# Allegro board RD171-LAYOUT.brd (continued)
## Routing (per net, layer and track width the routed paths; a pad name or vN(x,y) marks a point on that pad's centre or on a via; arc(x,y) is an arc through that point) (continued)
CS: length 14.7
  CONDUCTIVE4 w0.6: v1(249.9,16.55) 249.45,16.55 249,17 249,24.8 v1(248.75,25.05)
  BOTTOM w0.4: v1(249.9,16.55) R67.2
  BOTTOM w0.6: v1(248.75,25.05) R185.2 248.75,27.6 248.05,28.3 D14.C
CSA: length 131.4
  TOP w0.3: 135.45,43.67 135.45,42.95 135,42.5 v1(129.4,42.5)
  TOP w0.4: v1(109.8,80.55) 109.8,79.3 109.2,78.7 TP2.1
  TOP w0.5: 136.7,43.9 D33.C 135.4,43.9
  TOP w0.8: D33.C 135.45,43.67
  CONDUCTIVE3 w0.3: v1(154.2,3.25) 150.45,3.25 150,3.7 150,34.95 144.5,40.45 131.45,40.45 v1(129.4,42.5) 129,42.1 118.68,42.1 108.45,52.33 108.45,79.2 v1(109.8,80.55)
  BOTTOM w0.3: 109.8,81.87 v1(109.8,80.55) ; v1(154.2,3.25) 154.2,1.95 153.95,1.7 153.34,1.7 ; 110.05,82.7 111.14,82.7
  BOTTOM w0.5: 111.14,82.7 111.3,82.7
  BOTTOM w0.58: 153.34,1.7 R170.1 153.14,1.7
  BOTTOM w1.1: 110.05,82.7 R7.2 109.8,81.87
CSB: length 103.6
  TOP w0.3: D31.C 150,39.35 150.35,39 v1(150.85,39)
  TOP w0.5: R83.1 D31.C
  TOP w0.6: v1(126.35,77.65) 124.7,77.65
  CONDUCTIVE3 w0.3: v1(153.3,4.2) 153.05,4.45 153.05,24.1 151.7,25.45 151.7,38.15 v1(150.85,39) 145,44.85 132.4,44.85 125.05,52.2 125.05,74.2 126.8,75.95 126.8,77.2 v1(126.35,77.65)
  BOTTOM w0.3: D12.C 128.45,81.05 127.6,80.2 ; v1(126.35,77.65) 126.35,78.05 127.55,79.25
  BOTTOM w0.4: 153.18,3.08 153.18,3.85 v1(153.3,4.2)
FG2: length 13.4
  TOP w2: C79.1 23.4,3.95 11.5,3.95
  vias: v2(8,4)
FG3: length 84.1
  TOP w1.45: 76.38,43.25 78.03,41.6 C64.1 ; 76.38,43.25 76.4,43.25 ; 76.38,43.25 C32.1 65.5,43.25 ; 61.25,48.5 C78.1
  CONDUCTIVE4 w1.45: C32.1 76.38,43.25 78.03,41.6 C64.1
  CONDUCTIVE5 w1.45: C64.1 78.03,41.6 76.38,43.25 C32.1
  BOTTOM w1.45: 65.5,43.25 C32.1 76.38,43.25 ; 76.4,43.25 78.05,41.6 C64.1 ; 61.25,48.5 C78.1
  vias: v2(63,45.5)
FG4: length 109.7
  TOP w2: v2(77.9,4) C31.1
  CONDUCTIVE4 w1.5: C63.1 111.1,1.25 80.1,1.25
  CONDUCTIVE5 w1.5: 80.1,1.25 111.1,1.25 C63.1
  BOTTOM w1.5: 80.1,1.25 111.1,1.25 C63.1
  BOTTOM w2: v2(77.9,4) C31.1
FG5: length 4.6
  BOTTOM w1.45: C101.2 178.25,2.15
  vias: v2(181.25,4)
FG6:
  vias: v2(314.5,4)
FG7:
  vias: v2(314.5,123)
GDA: length 51.6
  TOP w0.3: 140.1,42.83 140.31,43.04 IC2.2 ; 140.1,42.83 139.95,42.67 139.95,42.4 ; 140.1,42.83 140.1,42.4 C81.2 ; 142,1.6 142.8,3.12 142.8,5.92 v1(142.2,6.53) ; 140.03,42.23 140.03,41.83 140.35,41.5 142.35,41.5 143.95,39.9 v1(143.95,36.2)
  TOP w0.45: 140.03,42.23 C81.2
  CONDUCTIVE3 w0.2: v1(142.2,6.53) 138.25,10.47 138.25,18.8 143.7,24.25 143.7,35.95 v1(143.95,36.2)
  BOTTOM w0.3: IC3.14 v1(142.2,6.53)
GDB: length 53.9
  TOP w0.3: C80.2 143.05,42.4 143.05,42.85 ; 143.2,42.5 143.2,42.7 143.05,42.85 ; 135.23,1.6 137.2,1.6 138.45,2.85 138.45,5.2 141.75,8.5 v1(142.2,8.5) ; 143.05,42.85 142.85,43.05 IC2.4 ; 143.12,42.23 143.12,41.62 145.1,39.65 v1(145.1,35.4)
  TOP w0.45: 143.12,42.23 C80.2
  TOP w1.7: 135.23,1.6 TP6.1
  CONDUCTIVE3 w0.2: v1(142.2,8.5) 142.2,9.05 139.65,11.6 139.65,17.89 145.1,23.34 v1(145.1,35.4)
  BOTTOM w0.3: IC3.17 141.8,8.47 v1(142.2,8.5)
HS1_1: length 6.5
  TOP w0.6: R224.2 v2(179.6,123)
HS1_2: length 6.3
  TOP w0.5: R225.2 v2(90.5,123)
IN: length 17.9
  TOP w0.3: C808.1 187.15,43.2
  TOP w0.95: 188.9,43.2 IC81.IN
  TOP w1: C804.2 196.24,36.36 189.4,43.2 D83.C 188.9,43.2
  BOTTOM w1.5: C804.2 199,35.9 199.55,35.35
LGND: length 306.5
  TOP w0.3: 255.76,15.85 254.8,16.81 v1(254.8,17.9) 254.8,17.95
  TOP w0.45: v1(255.45,100.55) 255.45,99.8 ; v1(255.45,62.45) 255.45,61.7
  TOP w0.6: 250.95,99.45 v1(250.95,97.35) C89.1 ; 263.2,17.7 263.85,17.7 264.1,17.45 v1(264.1,17.05) ; 263.2,17.7 R180.1 R52.1 R181.1 R50.1 ; 263.2,17.7 R51.1 R53.1 R182.1 ; R208.1 251.7,12.35 v1(251.4,12.35) ; v1(267.3,11.85) 267.2,11.95 R184.1 ; v1(261.15,60.05) 261.15,60.4 261.49,60.73 262.5,60.73 ; v1(251.4,15.15) 251.7,14.85 252.25,14.85 ; v1(249.95,99.5) 250.95,99.5 ; v1(247.2,16.5) R197.2 ; R55.1 267.1,15.15 v1(267.35,15.15) ; v1(247.2,21.3) R196.2 ; v1(249.95,61.4) 250.95,61.4 ; C90.1 v1(250.95,59.25) 250.95,61.35 ; v1(263.15,24.5) 263.15,23.55 ; v1(260.95,98.1) 260.95,98.39 261.4,98.83 IC6.3
  TOP w0.8: 314.12,66.65 313.5,67.27 C5.1
  TOP w1: C9.1 304.5,121.5 ; C9.1 306,120 ; C9.1 303,120 ; C8.1 294,121.2 ; C8.1 291,121.2 ; C8.1 292.5,122.7 ; C3.1 313.5,90.5 ; C3.1 315,92 ; C3.1 313.5,93.5 ; C4.1 313.5,81.5 ; C4.1 313.5,78.5 ; C4.1 315,80 ; 314.85,68 C5.1 313.5,69.5 ; C2.1 313.5,105.5 ; C2.1 313.5,102.5 ; C2.1 315,104
  TOP w2: CN7.2 310.5,21.9 ; CN7.2 312.8,18.2 ; CN7.2 308,18.2 ; CN7.2 310.5,14.1 ; CN7.1 301.5,14.2 ; CN7.1 301.5,21.9 ; CN7.1 299,18.2 ; CN7.1 304,18.2
  CONDUCTIVE2 w0.4: C809.1 251.05,3.9 ; C809.1 251.1,5.65 ; C809.1 249.35,3.9 ; C809.1 249.35,5.6 ; CN10.2 277.9,21.47 ; CN10.2 277.9,19.77 ; CN10.2 276.2,19.77 ; CN10.2 276.2,21.47 ; CN9.2 268.85,2.8 ; CN9.2 270.65,4.6 ; CN9.2 268.85,4.6 ; CN9.2 270.65,2.8 ; CN8.2 259.85,2.8 ; CN8.2 261.65,4.6 ; CN8.2 261.65,2.8 ; CN8.2 259.85,4.6 ; TP42.1 277.6,7.1 ; TP42.1 275.8,8.9 ; TP42.1 277.6,8.9 ; TP42.1 275.8,7.1
  CONDUCTIVE2 w0.5: C9.1 303.65,120.85 ; C9.1 305.35,119.15 ; C9.1 305.35,120.85 ; C9.1 303.65,119.15 ; TP41.1 314.1,112.2 ; TP41.1 315.9,114 ; TP41.1 315.9,112.2 ; TP41.1 314.1,114 ; C8.1 293.35,120.35 ; C8.1 291.65,122.05 ; C8.1 291.65,120.35 ; C8.1 293.35,122.05 ; C5.1 312.65,67.15 ; C5.1 312.6,68.9 ; C5.1 314.35,68.85 ; C5.1 314.35,67.15 ; C4.1 312.65,79.15 ; C4.1 312.6,80.9 ; C4.1 314.35,79.15 ; C4.1 314.35,80.85 ; C2.1 314.35,104.85 ; C2.1 312.6,104.9 ; C2.1 314.35,103.15 ; C2.1 312.65,103.15 ; C3.1 314.35,92.85 ; C3.1 314.35,91.15 ; C3.1 312.6,92.9 ; C3.1 312.65,91.15
  CONDUCTIVE4 w0.6: v1(245.55,25.05) 247,25.05 248.1,23.95 248.1,16.65 249.6,15.15 v1(249.9,15.15)
  CONDUCTIVE5 w0.4: C809.1 249.35,5.6 ; C809.1 249.3,3.85 ; C809.1 251.05,3.9 ; C809.1 251.05,5.6 ; CN8.2 261.65,2.8 ; CN8.2 261.65,4.6 ; CN8.2 259.85,4.6 ; CN8.2 259.85,2.8 ; CN10.2 277.93,21.5 ; CN10.2 277.9,19.77 ; CN10.2 276.2,19.77 ; CN10.2 276.2,21.47 ; TP42.1 277.6,7.1 ; TP42.1 277.6,8.9 ; TP42.1 275.8,7.1 ; TP42.1 275.8,8.9 ; CN9.2 268.85,4.6 ; CN9.2 270.65,2.8 ; CN9.2 270.65,4.6 ; CN9.2 268.85,2.8
  CONDUCTIVE5 w0.5: C5.1 312.6,68.9 ; C5.1 314.35,67.15 ; C5.1 312.65,67.15 ; C5.1 314.35,68.85 ; C4.1 314.35,80.85 ; C4.1 312.65,79.15 ; C4.1 312.6,80.9 ; C4.1 314.35,79.15 ; TP41.1 315.9,112.2 ; TP41.1 314.1,114 ; TP41.1 314.1,112.2 ; TP41.1 315.9,114 ; C8.1 291.65,122.05 ; C8.1 293.35,122.05 ; C8.1 293.35,120.35 ; C8.1 291.65,120.35 ; C9.1 303.65,119.15 ; C9.1 305.35,120.85 ; C9.1 305.35,119.15 ; C9.1 303.65,120.85 ; C3.1 314.35,91.15 ; C3.1 312.65,91.15 ; C3.1 312.6,92.9 ; C3.1 314.35,92.85 ; C2.1 312.6,104.9 ; C2.1 314.35,103.15 ; C2.1 312.65,103.15 ; C2.1 314.35,104.85
  BOTTOM w0.45: v1(254.8,23.1) 254.8,22.32 253.7,22.32 v1(253.7,23.1) ; C26.1 v1(254.8,17.9) ; v1(260.35,23.15) 261.23,23.15 ; v1(264.1,17.05) 264.15,17.1 264.45,17.1 264.68,17.32 C25.1
  BOTTOM w0.6: v1(260.95,98.1) 262,97.05 R21.1 ; v1(260.8,10.95) 260.8,11.8 ; v1(245.55,25.05) R185.1 ; v1(247.2,21.3) R194.2 ; v1(256.4,22.85) 256.4,22.05 ; v1(267.35,15.15) 267.15,14.95 266.7,14.95 R56.1 ; v1(247.2,16.5) R195.2 ; 263.75,54.3 v1(262.9,54.3) ; R22.1 256.8,70.1 ; v1(268.15,22.05) R45.1 ; v1(257.9,57.1) D29.A ; R19.1 256.8,108.1 ; v1(253.7,23.1) v1(254.8,23.1) ; v1(253.9,96.55) D26.A ; 267.65,20.35 v1(265.5,20.35) R48.1 ; C100.1 289.3,30.45 v1(289.3,30.3) 289.3,29.6 289.65,29.25 291.1,29.25 v1(291.25,29.4) IC8.2 ; v1(251.4,12.35) R64.1 ; v1(245.35,31.95) R9.1 ; v1(251.4,15.15) R66.1 ; v1(267.3,11.85) 266.45,11.85
  BOTTOM w1: C8.1 292.5,122.7 ; C8.1 291,121.2 ; C8.1 294,121.2 ; C2.1 313.5,105.5 ; C2.1 315,104 ; C2.1 313.5,102.5 ; C3.1 313.5,93.5 ; C3.1 315,92 ; C3.1 313.5,90.5 ; C5.1 313.5,66.5 ; C5.1 313.5,69.5 ; C5.1 315,68 ; C9.1 306,120 ; C9.1 303,120 ; C9.1 304.5,121.5 ; C4.1 313.5,78.5 ; C4.1 315,80 ; C4.1 313.5,81.5
  BOTTOM w2: CN7.2 310.5,14.2 ; CN7.2 313,18.2 ; CN7.2 310.5,22 ; CN7.2 308,18.2 ; CN7.1 299,18.2 ; CN7.1 301.5,22 ; CN7.1 304,18.2 ; CN7.1 301.5,14.2
  vias: v1(243.25,2.85) v1(243.25,1.95) v1(256.2,116.9) v1(256.2,116.05) v1(256.2,78.9) v1(256.2,78.05) v1(256.65,108) v1(256.65,107.1) v1(256.65,106.2) v1(256.65,105.3) v1(256.65,104.4) v1(256.65,103.5) v1(256.65,102.6) v1(256.65,70) v1(256.65,69.1) v1(256.65,68.2) v1(256.65,67.3) v1(256.65,66.4) v1(256.65,65.5) v1(256.65,64.6) v1(257.05,116.9) v1(257.05,116.05) v1(257.05,78.9) v1(257.05,78.05) v1(257.55,108) v1(257.55,107.1) v1(257.55,106.2) v1(257.55,105.3) v1(257.55,104.4) v1(257.55,103.5) v1(257.55,102.6) v1(257.55,70) v1(257.55,69.1) v1(257.55,68.2) v1(257.55,67.3) v1(257.55,66.4) v1(257.55,65.5) v1(257.55,64.6) v1(257.85,82.35) v1(258.1,124.3) v1(258.1,123.4) v1(258.1,122.5) v1(258.1,121.6) v1(258.1,120.7) v1(258.05,87.75) v1(258.05,86.85) v1(258.05,85.95) v1(258.05,85.05) v1(258.05,84.15) v1(258.05,83.25) v1(258.45,108) v1(258.45,107.1) v1(258.45,106.2) v1(258.45,105.3) v1(258.45,104.4) v1(258.45,103.5) v1(258.45,102.6) v1(258.45,70) v1(258.45,69.1) v1(258.45,68.2) v1(258.45,67.3) v1(258.45,66.4) v1(258.45,65.5) v1(258.45,64.6) v1(258.7,82.35) v1(258.95,87.75) v1(258.95,86.85) v1(258.95,85.95) v1(258.95,85.05) v1(258.95,84.15) v1(258.95,83.25) v1(259,125.2) v1(259,124.3) v1(259,123.4) v1(259,122.5) v1(259,121.6) v1(259,120.7) v1(259.35,108) v1(259.35,107.1) v1(259.35,106.2) v1(259.35,105.3) v1(259.35,104.4) v1(259.35,103.5) v1(259.35,102.6) v1(259.35,70) v1(259.35,69.1) v1(259.35,68.2) v1(259.35,67.3) v1(259.35,66.4) v1(259.35,65.5) v1(259.35,64.6) v1(259.6,116.05) v1(259.6,115.2) v1(259.55,82.35) v1(259.6,78.05) v1(259.6,77.2) v1(259.9,125.2) v1(259.9,124.3) v1(259.9,123.4) v1(259.9,122.5) v1(259.9,121.6) v1(259.9,120.7) v1(259.85,87.75) v1(259.85,86.85) v1(259.85,85.95) v1(259.85,85.05) v1(259.85,84.15) v1(259.85,83.25) v1(260.25,106.2) v1(260.25,105.3) v1(260.25,104.4) v1(260.25,103.5) v1(260.25,102.6) v1(260.25,68.2) v1(260.25,67.3) v1(260.25,66.4) v1(260.25,65.5) v1(260.25,64.6) v1(260.45,116.05) v1(260.45,115.2) v1(260.4,82.35) v1(260.45,78.05) v1(260.45,77.2) v1(260.8,125.2) v1(260.8,124.3) v1(260.8,123.4) v1(260.8,122.5) v1(260.8,121.6) v1(260.8,120.7) v1(260.75,86.85) v1(260.75,85.95) v1(260.75,85.05) v1(260.75,84.15) v1(260.75,83.25) v1(261.15,106.2) v1(261.15,105.3) v1(261.15,104.4) v1(261.15,103.5) v1(261.15,102.6) v1(261.15,68.2) v1(261.15,67.3) v1(261.15,66.4) v1(261.15,65.5) v1(261.15,64.6) v1(261.25,82.35) v1(261.65,85.95) v1(261.65,85.05) v1(261.65,84.15) v1(261.65,83.25) v1(261.7,125.2) v1(261.7,124.3) v1(261.7,123.4) v1(261.7,122.5) v1(261.7,121.6) v1(261.7,120.7) v1(262.05,106.15) v1(262.05,105.3) v1(262.05,104.4) v1(262.05,103.5) v1(262.1,82.35) v1(262.05,68.15) v1(262.05,67.3) v1(262.05,66.4) v1(262.05,65.5) v1(262.6,125.2) v1(262.6,124.3) v1(262.6,123.4) v1(262.6,122.5) v1(262.6,121.6) v1(262.6,120.7) v1(262.55,85.05) v1(262.55,84.15) v1(262.55,83.25) v1(262.95,82.35) v1(263.45,84.15) v1(263.45,83.25) v1(263.5,125.2) v1(263.5,124.3) v1(263.5,123.4) v1(263.5,122.5) v1(263.5,121.6) v1(263.5,120.7) v1(263.8,82.35) v1(264.3,83.25) v1(264.4,124.3) v1(264.65,82.35) v1(264.9,125.15) v1(269.9,125.15) v1(274.9,125.15) v1(279.9,125.15) v1(284.9,125.15) v1(289.9,125.15) v1(294.9,125.15) v1(295,28.85) v1(295,27.65) v1(295,26.45) v1(295,25.25) v1(295,24.05) v1(295,22.85) v1(295,21.65) v1(295,20.45) v1(295,19.25) v1(295,18.05) v1(295,16.85) v1(295,15.65) v1(295,14.45) v1(295,13.25) v1(295,12.05) v1(295,10.85) v1(295,9.65) v1(295,8.45) v1(295,7.25) v1(295.6,28.25) v1(295.6,24.65) v1(295.6,23.45) v1(295.6,22.25) v1(295.6,21.05) v1(295.6,19.85) v1(295.6,18.65) v1(295.6,17.45) v1(295.6,16.25) v1(295.6,15.05) v1(295.6,13.85) v1(295.6,12.65) v1(295.6,11.45) v1(295.6,10.25) v1(295.6,9.05) v1(295.6,7.85) v1(296,123.4) v1(296.2,28.85) v1(296.2,24.05) v1(296.2,22.85) v1(296.2,21.65) v1(296.2,20.45) v1(296.2,19.25) v1(296.2,18.05) v1(296.2,16.85) v1(296.2,15.65) v1(296.2,14.45) v1(296.2,13.25) v1(296.2,12.05) v1(296.2,10.85) v1(296.2,9.65) v1(296.2,8.45) v1(296.2,7.25) v1(296.8,28.25) v1(296.8,23.45) v1(296.8,22.25) v1(296.8,21.05) v1(296.8,19.85) v1(296.8,18.65) v1(296.8,17.45) v1(296.8,16.25) v1(296.8,15.05) v1(296.8,13.85) v1(296.8,12.65) v1(296.8,11.45) v1(296.8,10.25) v1(296.8,9.05) v1(296.8,7.85) v1(296.9,123.4) v1(296.9,122.5) v1(297.4,28.85) v1(297.4,24.05) v1(297.4,22.85) v1(297.4,21.65) v1(297.4,20.45) v1(297.4,19.25) v1(297.4,18.05) v1(297.4,16.85) v1(297.4,15.65) v1(297.4,14.45) v1(297.4,13.25) v1(297.4,12.05) v1(297.4,10.85) v1(297.4,9.65) v1(297.4,8.45) v1(297.4,7.25) v1(297.8,123.4) v1(297.8,122.5) v1(297.8,121.6) v1(297.8,120.7) v1(298,28.25) v1(298,23.45) v1(298,22.25) v1(298,21.05) v1(298,19.85) v1(298,18.65) v1(298,17.45) v1(298,16.25) v1(298,15.05) v1(298,13.85) v1(298,12.65) v1(298,11.45) v1(298,10.25) v1(298,9.05) v1(298,7.85) v1(298.25,119.8) v1(298.6,28.85) v1(298.6,27.65) v1(298.6,24.05) v1(298.6,22.85) v1(298.6,21.65) v1(298.6,20.45) v1(298.6,19.25) v1(298.6,18.05) v1(298.6,16.85) v1(298.6,15.65) v1(298.6,14.45) v1(298.6,13.25) v1(298.6,12.05) v1(298.6,10.85) v1(298.6,9.65) v1(298.6,8.45) v1(298.6,7.25) v1(298.7,123.4) v1(298.7,122.5) v1(298.7,121.6) v1(298.7,120.7) v1(299.15,119.8) v1(299.2,28.25) v1(299.2,27.05) v1(299.2,25.85) v1(299.2,24.65) v1(299.2,23.45) v1(299.2,22.25) v1(299.2,21.05) v1(299.2,19.85) v1(299.2,18.65) v1(299.2,17.45) v1(299.2,16.25) v1(299.2,15.05) v1(299.2,13.85) v1(299.2,12.65) v1(299.2,11.45) v1(299.2,10.25) v1(299.2,9.05) v1(299.2,7.85) v1(299.6,123.4) v1(299.6,122.5) v1(299.6,121.6) v1(299.6,120.7) v1(299.8,28.85) v1(299.8,27.65) v1(299.8,26.45) v1(299.8,25.25) v1(299.8,24.05) v1(299.8,22.85) v1(299.8,14.45) v1(299.8,13.25) v1(299.8,12.05) v1(299.8,10.85) v1(299.8,9.65) v1(299.8,8.45) v1(299.8,7.25) v1(299.9,125.15) v1(300.4,28.25) v1(300.4,27.05) v1(300.4,25.85) v1(300.4,24.65) v1(300.4,23.45) v1(300.4,22.25) v1(300.4,13.85) v1(300.4,12.65) v1(300.4,11.45) v1(300.4,10.25) v1(300.4,9.05) v1(300.4,7.85) v1(300.5,123.4) v1(300.5,122.5) v1(300.5,121.6) v1(301,28.85) v1(301,27.65) v1(301,26.45) v1(301,25.25) v1(301,24.05) v1(301,22.85) v1(301,13.25) v1(301,12.05) v1(301,10.85) v1(301,9.65) v1(301,8.45) v1(301,7.25) v1(301.4,123.4) v1(301.4,122.5) v1(301.6,28.25) v1(301.6,27.05) v1(301.6,25.85) v1(301.6,24.65) v1(301.6,23.45) v1(301.6,13.85) v1(301.6,12.65) v1(301.6,11.45) v1(301.6,10.25) v1(301.6,9.05) v1(301.6,7.85) v1(302.2,28.85) v1(302.2,27.65) v1(302.2,26.45) v1(302.2,25.25) v1(302.2,24.05) v1(302.2,22.85) v1(302.2,13.25) v1(302.2,12.05) v1(302.2,10.85) v1(302.2,9.65) v1(302.2,8.45) v1(302.2,7.25) v1(302.3,123.4) v1(302.8,27.05) v1(302.8,25.85) v1(302.8,24.65) v1(302.8,23.45) v1(302.8,22.25) v1(302.8,13.85) v1(302.8,12.65) v1(302.8,11.45) v1(302.8,10.25) v1(302.8,9.05) v1(302.8,7.85) v1(303.4,27.65) v1(303.4,26.45) v1(303.4,25.25) v1(303.4,24.05) v1(303.4,22.85) v1(303.4,14.45) v1(303.4,13.25) v1(303.4,12.05) v1(303.4,10.85) v1(303.4,9.65) v1(303.4,8.45) v1(303.4,7.25) v1(304,27.05) v1(304,25.85) v1(304,24.65) v1(304,23.45) v1(304,22.25) v1(304,13.85) v1(304,12.65) v1(304,11.45) v1(304,10.25) v1(304,9.05) v1(304,7.85) v1(304.6,27.65) v1(304.6,26.45) v1(304.6,25.25) v1(304.6,24.05) v1(304.6,22.85) v1(304.6,14.45) v1(304.6,13.25) v1(304.6,12.05) v1(304.6,10.85) v1(304.6,9.65) v1(304.6,8.45) v1(304.6,7.25) v1(304.9,125.15) v1(305.2,27.05) v1(305.2,25.85) v1(305.2,24.65) v1(305.2,23.45) v1(305.2,22.25) v1(305.2,13.85) v1(305.2,12.65) v1(305.2,11.45) v1(305.2,10.25) v1(305.2,9.05) v1(305.2,7.85) v1(305.8,27.65) v1(305.8,26.45) v1(305.8,25.25) v1(305.8,24.05) v1(305.8,22.85) v1(305.8,14.45) v1(305.8,13.25) v1(305.8,12.05) v1(305.8,10.85) v1(305.8,9.65) v1(305.8,8.45) v1(305.8,7.25) v1(306.4,27.05) v1(306.4,25.85) v1(306.4,24.65) v1(306.4,23.45) v1(306.4,22.25) v1(306.4,13.85) v1(306.4,12.65) v1(306.4,11.45) v1(306.4,10.25) v1(306.4,9.05) v1(306.4,7.85) v1(307,27.65) v1(307,26.45) v1(307,25.25) v1(307,24.05) v1(307,22.85) v1(307,14.45) v1(307,13.25) v1(307,12.05) v1(307,10.85) v1(307,9.65) v1(307,8.45) v1(307,7.25) v1(307.6,28.25) v1(307.6,27.05) v1(307.6,25.85) v1(307.6,24.65) v1(307.6,23.45) v1(307.6,22.25) v1(307.6,13.85) v1(307.6,12.65) v1(307.6,11.45) v1(307.6,10.25) v1(307.6,9.05) v1(307.6,7.85) v1(308.2,28.85) v1(308.2,27.65) v1(308.2,26.45) v1(308.2,25.25) v1(308.2,24.05) v1(308.2,22.85) v1(308.2,14.45) v1(308.2,13.25) v1(308.2,12.05) v1(308.2,10.85) v1(308.2,9.65) v1(308.2,8.45) v1(308.2,7.25) v1(308.6,123.6) v1(308.8,28.25) v1(308.8,27.05) v1(308.8,25.85) v1(308.8,24.65) v1(308.8,23.45) v1(308.8,22.25) v1(308.8,13.85) v1(308.8,12.65) v1(308.8,11.45) v1(308.8,10.25) v1(308.8,9.05) v1(308.8,7.85) v1(309.4,28.85) v1(309.4,27.65) v1(309.4,26.45) v1(309.4,25.25) v1(309.4,24.05) v1(309.4,22.85) v1(309.4,13.25) v1(309.4,12.05) v1(309.4,10.85) v1(309.4,9.65) v1(309.4,8.45) v1(309.4,7.25) v1(309.9,125.15) v1(310,28.25) v1(310,27.05) v1(310,25.85) v1(310,24.65) v1(310,23.45) v1(310,13.85) v1(310,12.65) v1(310,11.45) v1(310,10.25) v1(310,9.05) v1(310.3,119.4) v1(310.3,118.5) v1(310.3,117.6) v1(310.3,116.7) v1(310.6,28.85) v1(310.6,27.65) v1(310.6,26.45) v1(310.6,25.25) v1(310.6,24.05) v1(310.6,22.85) v1(310.6,13.25) v1(310.6,12.05) v1(310.6,10.85) v1(310.6,9.65) v1(311.2,28.25) v1(311.2,27.05) v1(311.2,25.85) v1(311.2,24.65) v1(311.2,23.45) v1(311.2,13.85) v1(311.2,12.65) v1(311.2,11.45) v1(311.3,119.4) v1(311.3,118.5) v1(311.3,117.6) v1(311.3,116.7) v1(311.3,115.8) v1(311.3,114.9) v1(311.3,114) v1(311.3,113.1) v1(311.3,112.2) v1(311.3,111.3) v1(311.8,28.85) v1(311.8,27.65) v1(311.8,26.45) v1(311.8,25.25) v1(311.8,24.05) v1(311.8,22.85) v1(311.8,13.25) v1(311.8,12.05) v1(312.2,118.5) v1(312.2,117.6) v1(312.2,116.7) v1(312.2,115.8) v1(312.2,114.9) v1(312.2,114) v1(312.2,113.1) v1(312.2,112.2) v1(312.2,111.3) v1(312.2,110.4) v1(312.4,28.25) v1(312.4,27.05) v1(312.4,25.85) v1(312.4,24.65) v1(312.4,23.45) v1(312.4,22.25) v1(312.4,15.05) v1(312.4,13.85) v1(312.4,12.65) v1(313,28.85) v1(313,27.65) v1(313,26.45) v1(313,25.25) v1(313,24.05) v1(313,22.85) v1(313,21.65) v1(313,20.45) v1(313,19.25) v1(313,18.05) v1(313,16.85) v1(313,15.65) v1(313,14.45) v1(313,13.25) v1(313.1,111.3) v1(313.1,110.4) v1(313.1,109.5) v1(313.3,74.9) v1(313.3,74) v1(313.3,73.1) v1(313.5,98.8) v1(313.5,97.9) v1(313.5,97) v1(313.5,86.9) v1(313.5,86) v1(313.5,85.1) v1(313.6,28.25) v1(313.6,27.05) v1(313.6,25.85) v1(313.6,24.65) v1(313.6,23.45) v1(313.6,22.25) v1(313.6,21.05) v1(313.6,19.85) v1(313.6,18.65) v1(313.6,17.45) v1(313.6,16.25) v1(313.6,15.05) v1(313.6,13.85) v1(314,110.4) v1(314,109.5) v1(314.2,74.9) v1(314.2,74) v1(314.2,73.1) v1(314.2,27.65) v1(314.2,26.45) v1(314.2,25.25) v1(314.2,24.05) v1(314.2,22.85) v1(314.2,21.65) v1(314.2,20.45) v1(314.2,19.25) v1(314.2,18.05) v1(314.2,16.85) v1(314.2,15.65) v1(314.2,14.45) v1(314.4,98.8) v1(314.4,97.9) v1(314.4,97) v1(314.4,86.9) v1(314.4,86) v1(314.4,85.1) v1(314.8,27.05) v1(314.8,25.85) v1(314.8,24.65) v1(314.8,23.45) v1(314.8,22.25) v1(314.8,21.05) v1(314.8,19.85) v1(314.8,18.65) v1(314.8,17.45) v1(314.8,16.25) v1(314.8,15.05) v1(314.9,110.4) v1(314.9,109.5) v1(314.9,108.6) v1(315.1,75.8) v1(315.1,74.9) v1(315.1,74) v1(315.1,73.1) v1(315.1,72.2) v1(315.3,99.7) v1(315.3,98.8) v1(315.3,97.9) v1(315.3,97) v1(315.3,96.1) v1(315.3,87.8) v1(315.3,86.9) v1(315.3,86) v1(315.3,85.1) v1(315.3,84.2) v1(315.4,27.65) v1(315.4,26.45) v1(315.4,25.25) v1(315.4,24.05) v1(315.4,22.85) v1(315.4,21.65) v1(315.4,20.45) v1(315.4,19.25) v1(315.4,18.05) v1(315.4,16.85) v1(315.4,15.65) v1(315.8,110.4) v1(315.8,109.5) v1(315.8,108.6) v1(315.8,107.7) v1(315.75,64.95) v1(316,76.7) v1(316,75.8) v1(316,74.9) v1(316,73.1) v1(316,72.2) v1(316,71.3) v1(316.2,99.7) v1(316.2,97.9) v1(316.2,97) v1(316.2,96.1) v1(316.2,87.8) v1(316.2,86.9) v1(316.2,86) v1(316.2,85.1) v1(316.6,118.7) v1(316.6,113.7) v1(316.6,109.05) v1(316.6,103.7) v1(316.6,98.7) v1(316.6,93.7) v1(316.6,88.7) v1(316.6,83.7) v1(316.6,78.7) v1(316.6,73.8) v1(316.6,68.7) v1(316.6,65.85) v1(316.6,64.95) v1(316.6,63.7) v1(316.6,58.7) v1(316.6,53.7) v1(316.6,48.7) v1(316.6,43.7) v1(316.6,38.7) v1(316.6,33.9)
OUTA1: length 154
  TOP w0.6: R111.1 143.8,109.5 v1(143.6,109.7)
  CONDUCTIVE3 w0.3: v1(143.6,109.7) 144.45,109.7 145.45,108.7 145.45,95.63 141.35,91.53 141.35,78 154.95,64.4 172.8,64.4 197.7,39.5 198.45,39.5 200.7,37.25 200.7,29.4 203.57,26.52 203.57,23.88 207.55,19.9 223.4,19.9 224.2,19.1 v1(224.7,19.1)
  BOTTOM w0.3: v1(224.7,19.1) 224.7,18.75 225.1,18.35 226.36,18.35 R187.2
  BOTTOM w0.4: 227.1,20.15 227.1,19.5 227,19.4 R187.2
OUTA2: length 10
  BOTTOM w0.3: R149.2 247.95,22.55 249.88,20.62 255.68,20.62
  BOTTOM w0.4: 255.68,20.62 IC10.22 256.44,20.62
OUTB1: length 154.2
  TOP w0.6: R110.1 143.8,106.1 v1(143.6,106.3)
  CONDUCTIVE3 w0.3: v1(224.7,15.05) 223.65,16.1 223.65,18.8 223.15,19.3 207.3,19.3 203.07,23.53 203.07,26.18 200.1,29.15 200.1,37 198.2,38.9 197.45,38.9 172.55,63.8 154.7,63.8 140.75,77.75 140.75,91.78 144.85,95.88 144.85,105.85 144.4,106.3 v1(143.6,106.3)
  BOTTOM w0.3: v1(224.7,15.05) 224.7,14.65 225,14.35 226.35,14.35 226.49,14.38 R189.2
  BOTTOM w0.4: R189.2 227,15.85 IC22.4
OUTB2: length 10.4
  BOTTOM w0.3: 255.68,19.98 249.88,19.98 248.5,18.6 248.5,18.1 248.2,17.8 247.42,17.8
  BOTTOM w0.4: 255.68,19.98 IC10.21 256.44,19.98
  BOTTOM w0.7: R150.2 247.42,17.8
OUTC1: length 95.5
  TOP w0.3: R113.1 162.6,60.5 163.95,60.5 165.15,61.7 168.82,61.7 v1(169.38,62.25) ; v1(222.9,18.55) 222.9,20.4 225.2,22.7 227.05,22.7
  TOP w0.4: IC23.4 227.05,21.85 227.25,22.05 227.25,22.7
  TOP w0.6: 227.25,22.7 227.05,22.7
  CONDUCTIVE3 w0.2: v1(169.38,62.25) 169.38,61.52 170.1,60.8 174.5,60.8 197.15,38.15 197.87,38.15 199.35,36.67 199.35,28.82 202.62,25.54 202.62,22.88 206.95,18.55 v1(222.9,18.55)
OUTC2: length 13
  TOP w0.3: v1(258.1,19.85) 257.9,19.65 248.6,19.65 248.25,20 247.32,20
  TOP w0.7: 247.32,20 R151.2
  BOTTOM w0.3: 257.03,19.32 257.5,19.32 257.77,19.6 v1(258.1,19.85)
  BOTTOM w0.4: 256.44,19.32 257.03,19.32
OUTD1: length 93.1
  TOP w0.3: 163.2,61.33 163.85,61.33 164.82,62.3 168.05,62.3 v1(168.85,63.1) ; v1(222.9,17.3) 223.95,18.35 226.25,18.35 226.4,18.5 227.08,18.5
  TOP w0.4: 227.29,18.5 227.29,17.75 227.05,17.5 IC24.4
  TOP w0.7: R193.2 227.08,18.5
  CONDUCTIVE3 w0.2: v1(168.85,63.1) 168.72,62.65 168.72,61.58 169.9,60.4 174.33,60.4 196.98,37.75 197.7,37.75 198.95,36.5 198.95,28.65 202.22,25.38 202.22,22.71 206.78,18.15 222.05,18.15 v1(222.9,17.3)
OUTD2: length 15.8
  TOP w0.3: v1(258.1,18.85) 248.65,18.85 248.3,18.5 248.3,15.6 247.9,15.2 247.38,15.2
  TOP w0.7: R152.2 247.38,15.2
  BOTTOM w0.3: v1(258.1,18.85) 257.73,18.68 257.06,18.68
  BOTTOM w0.4: 257.06,18.68 256.44,18.68
OUTE: length 105.5
  TOP w0.2: 263.04,59.45 263.65,59.45 263.9,59.7 263.9,62.4 264.85,63.35 269.8,63.35
  TOP w0.3: 261.95,59.45 261.37,59.28 261.08,58.99 v1(260.95,58.6) ; v1(260.95,96.7) 261.08,97.09 261.37,97.38 261.95,97.55
  TOP w0.57: 262.55,59.45 263.04,59.45
  TOP w1.7: 269.8,63.35 TP25.1
  CONDUCTIVE4 w0.3: v1(260.95,96.7) 260.95,95.12 253.6,87.77 253.6,61.75 256,59.35 260.2,59.35 v1(260.95,58.6)
  CONDUCTIVE4 w0.4: v1(260.95,58.6) 260.95,58.15 260.6,57.8 260.6,44.78 257.9,42.08 257.9,21.55 257.25,20.9 257.25,18.55 257.75,18.05 v1(258.1,17.85)
  BOTTOM w0.3: 257.12,18.02 257.73,18.02 v1(258.1,17.85)
  BOTTOM w0.4: 256.44,18.02 257.12,18.02
OUTF: length 108.6
  TOP w0.3: v1(259.9,58.55) 259.9,61.2 260.7,62 261.82,62 ; v1(259.9,97.4) 259.9,99.3 260.7,100.1 261.82,100.1 ; 265.25,102.6 265.25,101.35 264,100.11 263.04,100.11
  TOP w0.59: 262.5,100.1 261.82,100.1 ; 261.82,62 262.5,62
  TOP w0.6: IC6.4 263.04,100.11
  TOP w1.7: 265.25,102.6 265.25,103.35
  CONDUCTIVE4 w0.3: v1(259.9,97.4) 259.9,94.92 253,88.02 253,61.5 255.75,58.75 259.55,58.75 v1(259.9,58.55)
  CONDUCTIVE4 w0.4: v1(259.9,58.55) 259.9,45.07 257.2,42.37 257.2,21.84 256.55,21.19 256.55,18.15 v1(258.1,16.6)
  BOTTOM w0.3: v1(258.1,16.6) 257.91,16.97 257.5,17.38 257.03,17.38
  BOTTOM w0.4: 256.44,17.38 257.03,17.38
PFC_OUT: length 427.1
  TOP w0.3: 160.95,3.57 v1(160.95,5.25)
  TOP w1.7: TP44.1 160.95,3.57
  TOP w3.5: 225.11,28.75 225.11,31.32 225.03,32.19 224.81,33.03 224.44,33.82 223.94,34.53 223.65,34.85 217.51,40.99 216.85,41.55 216.09,41.98 215.27,42.28 214.41,42.43 213.98,42.45 203.57,42.45 202.63,42.49 200.75,42.82 198.97,43.47 197.32,44.42 195.87,45.64 190.02,51.49 189.36,52.05 188.6,52.48 187.78,52.78 186.92,52.93 186.49,52.95 178.57,52.95 177.7,52.87 176.86,52.65 176.07,52.28 175.36,51.78 175.04,51.49 165.26,41.71 164.7,41.05 164.27,40.29 163.97,39.47 163.82,38.61 163.8,38.18 163.8,37.57 163.78,37.14 163.63,36.28 163.33,35.46 162.9,34.7 162.34,34.04 C1.2
  BOTTOM w0.3: v1(160.95,5.25) 160.95,9.05 158.55,11.45 158.55,12.2 ; 164.75,26.4 165.2,25.95 ; 165.2,25.95 165.2,27.15 ; 165.2,25.95 165.65,26.4 ; 165.2,25.95 165.2,25.45 163.7,23.95 163.7,16.25 159.7,12.25 158.8,12.25
  BOTTOM w0.6: 158.8,12.25 158.6,12.25
  BOTTOM w2: 125.6,29.65 C7.2 ; 174.85,15.65 174.85,24.15 171.85,27.15 165.2,27.15 165.2,27.9
  BOTTOM w3: 136.2,30.7 136.2,47.85 135.18,48.87 D1.C 135.18,56.7 ; 166.38,56.7 D2.C 166.38,52.4 161.5,47.52 161.5,34.05
  BOTTOM w3.5: 225.11,28.75 225.11,31.32 225.03,32.19 224.81,33.03 224.44,33.82 223.94,34.53 223.65,34.85 217.51,40.99 216.85,41.55 216.09,41.98 215.27,42.28 214.41,42.43 213.98,42.45 203.57,42.45 202.63,42.49 200.75,42.82 198.97,43.47 197.32,44.42 195.87,45.64 190.02,51.49 189.36,52.05 188.6,52.48 187.78,52.78 186.92,52.93 186.49,52.95 178.57,52.95 177.7,52.87 176.86,52.65 176.07,52.28 175.36,51.78 175.04,51.49 167.16,43.61 166.6,42.95 166.17,42.19 165.87,41.37 165.72,40.51 165.7,40.08 165.7,29.4 163.7,29.4 ; 163.7,29.4 C1.2 ; 163.7,29.4 165.2,27.9
  BOTTOM w7: 125.55,29.65 135.25,29.65 137.3,27.6 150.45,27.6 152.5,29.65 157.9,29.65 ; 125.6,29.7 121.45,29.7 102.5,48.65 102.5,74.35 98.45,78.4 98.45,108.5 100.95,111 100.95,117.4
PFC_VIN: length 8.8
  TOP w0.5: 123.92,118.4 124.58,119.05 v1(125.05,119.05) v1(126.3,119.05)
  TOP w1: 123.92,118.4 123.92,114.9
  BOTTOM w0.5: 123.9,118.34 124.61,119.05 v1(125.05,119.05) v1(126.3,119.05)
PN: length 634.5
  TOP w0.3: v1(145.05,6.45) 145.46,6.5 R175.1 146.01,6.5 ; 154.91,44.9 R71.1 v1(153.95,44.9) ; v1(88.8,74.8) 88.8,75.4
  TOP w0.4: IC24.3 229.15,17.05 229.6,17.5 v1(229.6,18.2) ; IC23.3 228.95,21.7 228.7,21.95 R191.1 ; 85.2,75.59 v1(85.2,74.5) ; 88.8,75.4 C70.1 88.8,75.55
  TOP w0.45: 233.28,18.62 C73.1 233.95,18.62 234.18,18.85 234.8,18.85 ; C98.1 225.6,17.5 v1(225.7,17.6) ; v1(231.6,14.95) 232.35,14.95 ; 132.2,45.6 v1(129.4,45.6) ; v1(188,44.45) 187.95,44.4 C808.2 ; C97.1 v1(225.6,21.9) ; C35.1 148.75,43.38 v1(148.75,43.75) ; R811.2 188.18,36.85 C805.2
  TOP w0.5: v1(119.4,46.8) 119.4,44.66 118.14,43.4 116.58,43.4 ; 82.87,123.93 v1(82.86,123.92) 82.86,123 ; IC5.5 148,105.83 ; 148,105.83 148,102.95 ; 148,105.83 148,108.07 148.3,108.37 IC5.3 149.45,108.37 ; v1(179.25,64.4) 179.25,65.25 180.8,66.8 181.32,66.8 ; 129.68,64.56 130.84,64.56 v1(130.9,64.5) ; v1(151.75,5.7) R176.1 ; 145.2,47.6 v1(145.95,47.6)
  TOP w0.6: 165.9,78.7 165.9,78.34 168.04,76.2 169.45,76.2 169.85,75.8 D25.A R33.1 ; 165.9,78.7 Q4.S ; 165.9,78.7 166.55,79.35 ; 165.9,78.7 165.25,79.35 ; v1(143,45.8) 142.3,45.8 141.59,45.09 IC2.3 ; v1(184.6,79.35) 184.6,80.25 ; v1(188.35,123) R224.1 ; C53.1 143.8,107.5 v1(143.6,107.3) ; IC15.4 234.22,23.1 v1(231.55,23.1) ; 167.37,64.5 167.37,63.12 v1(167.35,63.1) 165.43,63.1 164.83,63.7 IC4.3 ; C57.1 v1(160.7,66.4) ; v1(229.6,23) 229,23 R191.1 ; v1(127.5,51.1) 125.65,51.1 ; R193.1 229.3,18.5 v1(229.6,18.2) ; v1(143.6,110.9) C54.1 ; 184.65,36.2 v1(184.65,33.65) 186,33.65 187.2,34.85 R811.2 ; v1(234.8,18.9) 234.75,18.85 IC16.4 234.75,17.75
  TOP w0.7: v1(145.95,47.6) 147.4,47.6 v1(147.7,47.3) C82.1 C83.1 ; R198.1 R174.1 144.45,12.1 143.35,13.2 v1(142.9,13.2) ; 116.58,43.4 R222.1 ; 181.32,66.8 R221.1 ; v1(148.75,43.75) 147.75,43.75
  TOP w0.72: 129.6,64.56 129.68,64.56
  TOP w0.885: 85.2,75.86 85.2,75.59
  CONDUCTIVE2 w0.4: TP45.1 167.6,2.9 ; TP45.1 167.6,1.1 ; TP45.1 165.8,2.9 ; TP45.1 165.8,1.1 ; TP43.1 122,3.2 ; TP43.1 120.8,2 ; TP43.1 122,0.8 ; TP43.1 123.2,2 ; C101.1 172.85,8.85 ; C101.1 174.05,10.05 174.85,10.05 ; C101.1 172.85,10.45 ; C101.1 174.45,8.85 ; IC20.2 86.7,72.65 ; IC20.2 86.7,70.95 ; IC20.2 85,72.65 ; IC20.2 85,70.95 ; C804.1 202.9,35.1 ; C804.1 201.3,35.1 ; C804.1 201.3,36.7 ; C804.1 202.9,36.7
  CONDUCTIVE2 w0.8: D18.A 186,116.55 ; D18.A 183.9,116.55 ; D18.A 183.9,114.45 ; D18.A 186,114.45 ; C103.1 159.95,96.75 ; C103.1 158.15,94.95 ; C103.1 158.15,96.75 ; C103.1 159.95,94.95
  CONDUCTIVE2 w1: Q2.S 141.4,57.6 ; Q2.S 141.45,54.85 ; Q2.S 144.1,54.9 ; Q2.S 144.1,57.5 ; 125.95,122.25 D3.4 ; D3.4 123.35,124.85 ; D3.4 123.4,122.2 ; D3.4 126,124.8 ; Q1.S 112.9,57.5 ; Q1.S 110.25,54.85 ; Q1.S 110.2,57.6 ; Q1.S 112.9,54.9 ; T8.4 204.73,26 ; T8.4 204.73,23.1 ; T8.4 203.3,24.5
  CONDUCTIVE2 w1.3: HS6.1 189.4,109.6 ; HS6.1 187.5,111.5 ; HS6.1 185.6,109.6 ; HS6.1 187.5,107.7 ; Q4.S 167.09,80.31 ; Q4.S 164.55,82.85 ; Q4.S 164.58,80.18 ; Q4.S 167.09,82.69 ; Q6.S 173.65,122.45 ; Q6.S 171.31,124.79 ; Q6.S 173.65,125.15 ; Q6.S 171.14,122.64 ; HS5.1 189.4,98.4 ; HS5.1 185.6,98.4 ; HS5.1 187.5,100.3 ; HS5.1 187.5,96.5
  CONDUCTIVE2 w1.5: C7.1 123.8,17.6 ; C7.1 127.35,21.15 ; C7.1 123.8,21.2 ; C7.1 127.35,17.65 ; C1.1 159.5,21.2 ; C1.1 155.9,17.6 ; C1.1 155.9,21.2 ; C1.1 159.5,17.6
  CONDUCTIVE3 w0.3: v1(151.8,4.5) 152.45,5.15 152.45,23.85 151.1,25.2 151.1,37.75 144.6,44.25 132.15,44.25 124.45,51.95 124.45,55.1 124.63,55.28 124.63,57.12 124.45,57.3 124.45,74.75 v1(126,76.3) ; v1(108.85,80.55) 107.85,79.55 107.85,52.08 118.43,41.5 129.4,41.5 131.05,39.85 144.25,39.85 149.4,34.7 149.4,3.75 v1(148.95,3.3)
  CONDUCTIVE5 w0.4: TP45.1 165.8,2.9 ; TP45.1 165.8,1.1 ; TP45.1 167.6,1.1 ; TP45.1 167.6,2.9 ; C101.1 174.05,10.05 174.7,10.05 ; C101.1 172.85,8.85 ; C101.1 174.45,8.85 ; C101.1 172.85,10.45 ; IC20.2 86.7,70.95 ; IC20.2 85,70.95 ; IC20.2 85,72.65 ; IC20.2 86.7,72.65 ; TP43.1 122,3.2 ; TP43.1 122,0.8 ; TP43.1 120.8,2 ; TP43.1 123.2,2 ; C804.1 201.3,36.7 ; C804.1 202.9,35.1 ; C804.1 201.3,35.1 ; C804.1 202.9,36.7
  CONDUCTIVE5 w0.8: C103.1 158.15,94.95 ; C103.1 158.15,96.75 ; C103.1 159.95,94.95 ; C103.1 159.95,96.75 ; D18.A 186,114.45 ; D18.A 183.9,114.45 ; D18.A 183.9,116.55 ; D18.A 186,116.55
  CONDUCTIVE5 w1: Q1.S 110.2,57.6 ; Q1.S 112.9,57.5 ; Q1.S 110.25,54.85 ; Q1.S 112.9,54.9 ; D3.4 123.35,124.85 ; D3.4 125.95,122.25 ; D3.4 126.05,124.85 ; D3.4 123.35,122.15 ; Q2.S 141.4,57.6 ; Q2.S 144.1,54.9 ; Q2.S 141.45,54.85 ; Q2.S 144.1,57.5 ; T8.4 204.73,23 ; T8.4 203.3,24.5 ; T8.4 204.73,26
  CONDUCTIVE5 w1.3: 171.31,124.79 Q6.S ; Q6.S 171.14,122.64 ; Q6.S 173.65,125.15 ; Q6.S 173.65,122.45 ; Q4.S 167.09,80.31 ; Q4.S 164.55,82.85 ; Q4.S 167.09,82.69 ; Q4.S 164.58,80.18 ; HS6.1 187.5,111.5 ; HS6.1 187.5,107.7 ; HS6.1 185.6,109.6 ; HS6.1 189.4,109.6 ; HS5.1 187.5,96.5 ; HS5.1 189.4,98.4 ; HS5.1 185.6,98.4 ; HS5.1 187.5,100.3
  CONDUCTIVE5 w1.5: C1.1 159.5,21.2 ; C1.1 155.9,17.6 ; C1.1 159.5,17.6 ; C1.1 155.9,21.2 ; C7.1 127.4,17.6 ; C7.1 123.8,21.2 ; C7.1 127.35,21.15 ; C7.1 123.8,17.6
  BOTTOM w0.3: v1(142.2,7.65) 141.85,7.83 IC3.16 139.55,7.83 ; 124.65,78.3 124.65,79.3 R8.1 ; 124.65,78.3 126,76.95 v1(126,76.3) ; 124.65,78.3 124.1,78.85 ; 139.55,7.83 C49.1 ; 139.55,7.83 139.12,7.4 138.85,7.4 C47.1
  BOTTOM w0.4: v1(229.6,18.2) 229.6,19.85 229.3,20.15 IC21.3 ; IC22.3 229.25,15.85 229.25,15 v1(229.3,14.95) ; R7.1 106.5,81.35 107.3,80.55 v1(108.85,80.55) C36.1 108.85,79.7 ; 151.72,14.8 151.2,14.8 150.95,14.55 150.95,12.62 150.15,11.82 C39.1
  BOTTOM w0.45: 138.82,7.33 C47.1 137.88,7.33 136.95,8.25 C48.1 ; C34.1 125.97,76.28 v1(126,76.3) ; C38.1 150.85,8.07 R102.1 ; v1(151.8,4.5) 151.05,4.5 ; v1(231.55,18.6) 232.32,18.6 ; v1(175.3,36.4) 175.32,36.42 C67.1 ; C43.1 138.62,4.2 ; 149.62,2.23 148.95,2.9 ; 148.95,2.9 v1(148.95,3.3) ; 148.95,2.9 148.7,3.15 ; 232.32,23.1 v1(231.55,23.1) ; v1(225.7,15.05) 225.7,15.8 ; 148.72,13.93 147.69,13.93 ; v1(225.7,19.1) 225.7,20.05 ; C45.1 v1(140.5,3.2) ; v1(148.45,11.05) 148.45,11.2 149.07,11.82 C39.1
  BOTTOM w0.5: R807.1 187.1,45.05 v1(186.55,45.6) 185.45,45.6 ; R104.1 147.45,15.65 146.85,16.25 v1(144.25,16.25)
  BOTTOM w0.55: 147.69,13.93 147.45,13.93
  BOTTOM w0.6: IC14.4 234.33,15.23 234.05,14.95 v1(231.6,14.95) ; v1(186.55,45.6) 186.55,46.2 186,46.75 ; 171.65,121.55 172.3,120.9 ; 172.3,120.9 172.95,121.55 ; 172.3,120.9 Q6.S ; 172.3,120.9 172.3,119.8 171.7,119.2 ; 228.45,18.55 228.8,18.2 v1(229.6,18.2) ; R2.1 152.05,5.4 v1(151.75,5.7) 151.65,5.8 R101.1 R102.1 ; C802.1 186.45,40.7 187,41.25 ; R99.1 140.75,2.35 140.5,2.6 v1(140.5,3.2) ; v1(167.35,63.1) C56.1 ; R807.1 187.1,43.74 187,43.65 IC80.GND 187,41.26 ; v1(234.8,18.9) 234.8,20.05 ; v1(188,44.45) 187.15,44.45 ; 171.7,119.2 171.7,118.7 ; 171.7,119.2 171.2,119.2 ; 171.7,118.7 D22.A ; 171.7,118.7 171.2,119.2 ; R189.1 228.65,14.75 229.1,14.75 v1(229.3,14.95) ; C803.1 188.95,38.95 v1(189.55,38.95) ; R96.1 C77.1 148.8,3.15 v1(148.95,3.3) ; C66.1 175.8,39.4 IC11.1 v1(173.45,39.4) ; 171.2,119.2 R29.1
  BOTTOM w0.7: v1(142.9,13.2) C40.1 ; v1(142.9,13.2) R93.1 ; v1(142.9,13.2) R103.1 R100.1 ; v1(136.55,3.3) R98.1 ; 151.72,14.8 R90.1
  BOTTOM w0.8: 136.95,8.95 134.75,8.95
  BOTTOM w1.5: TP45.1 166.7,7.9 168.15,9.35 168.15,11.95
  vias: v1(124.15,42.85) v1(144.1,103) v1(144.1,101.75) v1(144.1,100.45) v1(145.75,93.3) v1(145.75,92.05) v1(170.35,62.4) v1(172.1,62.83) v1(172.1,61.5) v1(195.35,29.95) v1(195.35,29.05) v1(196.25,33.8) v1(196.25,32.9) v1(196.25,32) v1(197.05,33.35) v1(197.05,32.45)
SIG1: length 179.1
  TOP w1.5: C78.2 F1.2
  TOP w5: F1.2 49.5,41.24 41.5,33.24 41.5,19.5 C30.2
  CONDUCTIVE4 w5: 41.5,22.25 41.5,19.5 C30.2 47.1,17.5 49.7,20.1 49.7,28.15
  CONDUCTIVE5 w5: 41.5,22.25 41.5,19.5 C30.2 47.1,17.5 49.7,20.1 49.7,28.15
  BOTTOM w1.1: 59.75,28.15 R79.2 49.7,28.15
  BOTTOM w1.5: C78.2 F1.2
  BOTTOM w5: F1.2 49.5,41.24 41.5,33.24 41.5,19.5 C30.2 47.5,17.5 49.7,19.7 49.7,30.05
SIG2: length 124.8
  TOP w5: RV1.2 33.9,24.75 ; 33.9,24.75 32.45,26.2 23.2,26.2 CN1.3 ; 33.9,24.75 31.95,22.8 C79.2 32.95,4 48.2,4 49.75,5.55 49.75,7.1
  BOTTOM w1.1: 59.65,12.25 55.15,12.25 51.1,8.2
  BOTTOM w5: RV1.2 33.9,24.75 ; 33.9,24.75 31.95,22.8 C79.2 32.95,4 48.2,4 49.75,5.55 49.75,7.1 ; 33.9,24.75 32.45,26.2 23.2,26.2 CN1.3
SIG6: length 307.6
  TOP w1: 121.08,118.4 121.08,119.33 117.2,123.2
  TOP w5: 77.55,85.6 76,85.6 69.3,92.3 69.3,111.85 C33.1 81.75,114 112.4,114 117.9,108.5 117.9,96.5 ; 107.65,9.75 110.5,12.6 ; 107.65,9.75 110.5,9.75 ; 107.65,9.75 L12.4
  TOP w7: 77.55,85.6 89.35,85.6 101.95,73 101.95,47.2 111.26,37.89 111.69,37.42 112.42,36.38 112.96,35.22 113.29,33.99 113.4,32.73 113.4,31.12 113.38,30.6 113.2,29.58 112.84,28.6 112.32,27.7 111.65,26.9 111.65,13.2
  CONDUCTIVE4 w5: C65.1 69.3,94.75 69.3,111.85 C33.1
  CONDUCTIVE5 w5: C65.1 69.3,94.75 69.3,111.85 C33.1
  BOTTOM w5: C65.1 69.3,94.75 69.3,111.85 C33.1
SIG8: length 165
  TOP w1: 109.7,123.2 112.1,120.8 113.38,120.8 119.28,114.9 121.08,114.9
  TOP w5: C65.2 73.3,64.3 76.1,61.5 84.4,61.5 86.45,59.45 86.45,58.3
  CONDUCTIVE4 w5: C65.2 73.3,77.5 80.8,85 80.8,94.45 77.6,97.65
  CONDUCTIVE5 w5: 77.6,97.65 80.8,94.45 80.8,85 73.3,77.5 C65.2
  BOTTOM w5: 88.45,96.5 88.3,96.65 78.75,96.65 ; 78.7,96.55 80.8,94.45 80.8,85 73.3,77.5 C65.2 73.3,64.3 76.1,61.5 84.4,61.5 86.45,59.45 86.45,58.3
SIG9: length 3.9
  BOTTOM w0.6: 59.06,22.9 59.06,24.85 ; IC1.3 60.34,24.85
SIG10: length 3.9
  BOTTOM w0.6: IC1.6 60.34,15.55 ; 59.06,17.5 59.06,15.55
SIG11: length 50.3
  BOTTOM w3: 142.1,70.38 144.72,70.38 153.3,61.8 156,61.8 161.3,56.5 D2.A
  BOTTOM w5: 141.7,71.97 141.7,72.98 135.57,79.11 135.57,93.17 136.55,94.15
SIG12: length 39.7
  BOTTOM w3: 121.3,70.45 126.2,65.55 126.2,60.6 127.8,59
  BOTTOM w5: 110.2,96.5 110.2,93.7 117.2,86.7 117.2,76.7 119.2,74.7
SIG15: length 9.6
  BOTTOM w0.3: T2.1 129.61,76.39 129.33,76.72 ; 129.25,78.52 129.25,77.85 129.1,77.7 R81.2
  BOTTOM w0.38: 129.26,76.8 129.33,76.72
  BOTTOM w0.8: 129.25,78.75 129.25,78.52
SIG16: length 1.9
  BOTTOM w0.3: 127.76,76.8 127.76,75.96 127.3,75.5 C34.2
SIG18: length 10.7
  BOTTOM w3: 142.45,64.45 148.25,58.65 148.25,56.2
SIG20: length 9
  BOTTOM w0.3: T3.1 111.1,77.3 111.4,77.6 111.4,78.72 ; 111.4,79 111.4,80.04
  BOTTOM w0.7: 111.4,79 R85.2 111.4,78.72
  BOTTOM w0.8: 111.4,80.25 111.4,80.04
SIG21: length 1.2
  BOTTOM w0.3: 109.02,78.78 109.8,78.78
  BOTTOM w0.45: C36.2 109.02,78.78
  BOTTOM w0.7: 109.8,78.78 110,78.78
SIG23: length 4.5
  TOP w0.3: 156.19,44.9 156.9,45.61 156.9,46.41
  TOP w0.8: R72.2 R108.2
  TOP w0.92: 156.9,46.8 156.9,46.41
SIG24: length 4.5
  TOP w0.45: C35.2 150.55,41.92
  TOP w0.5: 152.3,40.35 152.15,40.5 R172.2
  TOP w0.7: R172.2 R82.2
SIG25: length 2.3
  TOP w0.5: 133.2,45.6 R173.2
  TOP w0.7: R173.2 R86.2
SIG27: length 6.7
  TOP w0.3: 123.55,49.7 123.55,50.39 124.26,51.1
  TOP w0.8: R109.2 R74.2 ; 123.6,46.6 121.8,46.6 FB2.1
  TOP w0.92: 123.55,49.7 R109.2
SIG30: length 13.3
  TOP w0.6: 139.1,47.75 139.72,47.75 140.31,48.35 IC2.7
  TOP w0.7: D32.C 135.8,47.75 135.25,48.3 R86.1 133.3,48.3 132.45,49.15 D39.C
  TOP w0.8: D38.A D39.C ; 139.1,47.75 D32.C
SIG39: length 1.3
  BOTTOM w0.4: R89.2 R91.1
SIG40: length 1.2
  BOTTOM w0.4: R91.2 R92.1
SIG43: length 3.6
  BOTTOM w0.3: 142.22,3.36 142.22,4.2 141.85,4.58 IC3.11
  BOTTOM w0.4: C45.2 143.25,3.2
  BOTTOM w0.45: C45.2 142.22,3.36
SIG44: length 1.3
  BOTTOM w0.4: C46.1 142.88,1.9 R99.2
SIG45: length 4.1
  BOTTOM w0.3: 139.57,3.71 139.57,4.92 139.88,5.22 140.72,5.22
  BOTTOM w0.4: 139.57,3.71 C43.2 C44.2
SIG46: length 1.2
  BOTTOM w0.4: R98.2 137.65,2.05 138.57,2.05 C44.1
SIG47: length 6.9
  BOTTOM w0.3: C40.2 145.1,11.8 145.8,12.5 145.8,13.03 ; 146.57,9.12 IC3.3 145.38,9.12 144.15,10.35 144.15,11.6
  BOTTOM w0.7: C40.2 144.15,11.6 ; 145.8,13.03 C41.2
SIG48: length 1.5
  BOTTOM w0.5: 145.55,14.95 R93.2 144.05,14.95
SIG49: length 23
  TOP w0.3: v1(145.05,8.5) 150.35,8.5 152.55,6.3 152.55,2.55 153.5,1.6
  BOTTOM w0.3: 146.57,8.47 147.62,8.47 149.55,10.4 149.55,10.74 ; 151.63,10.85 149.72,10.85 ; 146.55,8.47 IC3.4 145.45,8.47 v1(145.05,8.5)
  BOTTOM w0.4: R89.1 R227.2 ; 149.72,10.85 149.55,10.85
  BOTTOM w0.45: 149.55,10.74 C39.2
  BOTTOM w0.7: R227.2 151.63,10.85
SIG50: length 2.3
  BOTTOM w0.3: 138.8,9.78 139.45,9.12 140.8,9.12
SIG51: length 5.3
  BOTTOM w0.3: 148.84,12.97 149.47,12.97 150.05,13.56 ; 147.1,10.85 148.75,12.5 148.75,12.84 ; 147.1,10.85 146.7,10.45 ; 147.1,10.85 147.1,10.43
  BOTTOM w0.45: 148.75,12.84 C50.2 148.84,12.97
SIG52: length 7.2
  TOP w0.3: v1(139.5,10.5) 140.5,9.5 142.91,9.5
  TOP w0.58: 143.11,9.5 R198.2 142.91,9.5
  BOTTOM w0.3: R100.2 139.5,11.2 v1(139.5,10.5) 139.5,10.07 139.8,9.78 IC3.19
SIG53: length 4.3
  TOP w0.3: R176.2 148.95,6.2 v1(148.45,6.2)
  BOTTOM w0.3: v1(148.45,6.2) 148.12,6.53 146.57,6.53
  BOTTOM w0.4: 149.3,5.8 148.85,5.8 v1(148.45,6.2)
  BOTTOM w0.6: 149.3,5.8 149.4,5.8
SIG54: length 4.3
  TOP w0.3: R175.2 148.05,7.2 v1(148.45,7.2)
  BOTTOM w0.3: 146.57,7.17 148.04,7.17 v1(148.45,7.2)
  BOTTOM w0.4: v1(148.45,7.2) 149.43,7.2
  BOTTOM w0.7: 149.43,7.2 R102.2
SIG55: length 4.2
  TOP w0.3: v1(142.2,10.43) 142.93,11.26
  TOP w0.7: 142.93,11.26 R174.2
  BOTTOM w0.3: R103.2 142.2,11.3 v1(142.2,10.43) IC3.20
SIG56: length 5.2
  BOTTOM w0.3: 146.57,9.78 IC3.2 145.57,9.78 145.2,10.15 145.2,10.75 145.95,11.5 146.29,11.5 147.26,12.47
  BOTTOM w0.58: 147.26,12.47 147.45,12.66
SIG60: length 1.2
  BOTTOM w0.5: 123.9,115.84 R94.2 R95.1 123.9,117.06
SIG61: length 168
  CONDUCTIVE3 w1: v1(155.3,3.4) 155.3,2.15 154.35,1.2 136.7,1.2 113,24.9 113,39.9 103.7,49.2 103.7,84.4 107.65,88.35 119,88.35 123.9,93.25 v1(123.9,113.1)
  BOTTOM w0.3: R1.2 154.35,8 155.3,7.05 v1(155.3,3.4)
  BOTTOM w0.5: v1(123.9,113.1) R94.1 123.9,114.56
SIG62: length 18
  TOP w0.3: 148.05,1.68 148.05,2.95 146,5 144.95,5 144.25,5.7 144.25,7.2 144.5,7.45 v1(145.05,7.45)
  TOP w1.7: 148.05,1.68 TP7.1
  BOTTOM w0.3: 146.55,7.83 IC3.5 145.43,7.83 v1(145.05,7.45) ; 150.38,9.32 149.5,9.32 148,7.83 146.57,7.83
  BOTTOM w0.4: R228.2 R1.1 ; C38.2 152.25,9.32
  BOTTOM w0.45: 150.38,9.32 C38.2
SIG65: length 7.1
  TOP w0.6: v1(163.55,67.65) 163.55,69.9
  BOTTOM w0.45: 163.97,66.92 163.55,67.35 v1(163.55,67.65) ; C19.2 163.97,66.38 164.25,66.1 166.75,66.1 166.75,66.6
SIG75: length 4.1
  TOP w0.45: C18.2 v1(156.3,109.65)
  TOP w0.6: IC5.13 156.3,109.64
  BOTTOM w0.6: v1(156.3,109.65) 156.3,111.35
SIG82: length 11
  BOTTOM w0.6: 161.45,120.75 160.8,121.4 ; 161.45,120.75 162.1,121.4 ; 161.45,120.75 161.45,123.77 ; 161.45,120.75 161.45,120.25 R29.2 R137.2 R136.2
SIG86: length 12.7
  TOP w0.6: v1(128.7,2) 127.85,2
  BOTTOM w0.3: IC3.15 139.95,7.17 139.15,6.38 C47.2
  BOTTOM w0.45: 137.32,5.83 137.88,6.38 C47.2
  BOTTOM w0.7: v1(128.7,2) 132.7,6 D49.C 134.8,6
SIG89: length 18.7
  TOP w0.3: v1(143.6,108.4) 145.5,108.4 145.9,108.8 R111.2 ; 148.62,110.91 146.12,110.91
  TOP w0.5: v1(138.4,113.6) 138.4,114.95
  TOP w0.6: IC5.1 148.62,110.91 ; R111.2 C54.2
  TOP w0.7: 146.12,110.91 145.9,110.91
  TOP w1.7: 138.4,114.95 TP38.1
  CONDUCTIVE3 w0.2: v1(138.4,113.6) 141.1,113.6 142.9,111.8 142.9,109.1 v1(143.6,108.4)
SIG90: length 28.9
  TOP w0.3: R110.2 145.9,105.4 145.5,105 v1(143.6,105) ; C53.2 148,109.6 148.78,109.6
  TOP w0.5: v1(132.1,113.6) 132.1,114.95
  TOP w0.52: 149.3,109.6 148.78,109.6
  TOP w0.6: C53.2 R110.2
  TOP w1.7: 132.1,114.95 TP39.1
  CONDUCTIVE3 w0.2: v1(143.6,105) 142.5,106.1 142.5,111.6 141.2,112.9 132.8,112.9 v1(132.1,113.6)
SIG91: length 2.3
  TOP w0.6: C85.2 175.8,65.3 174.9,66.2
SIG92: length 3
  TOP w0.6: 171.6,66.25 171.1,65.75 v1(171.1,65.1)
  BOTTOM w0.6: v1(171.1,65.1) 171.1,66.7
SIG93: length 6.6
  TOP w0.3: 162.29,64.08 162.29,63.45 R113.2 161.1,62.7 160.7,63.1 160.7,63.85 ; 160.68,64.06 159.79,64.06 159.68,63.95 159.62,63.89 158.7,63
  TOP w0.58: 160.7,64.06 160.68,64.06
  TOP w0.6: 160.7,64.05 C57.2 160.7,63.85 ; IC4.1 162.29,64.08
SIG94: length 19.9
  TOP w0.3: v1(164.15,63.1) 163.75,62.7 R112.2 163.55,63.6 163.55,64.06 ; 153.68,64 155.75,64 158.95,67.2 v1(159.75,67.2)
  TOP w0.58: 163.55,64.55 163.55,64.06
  TOP w1.7: 153.68,64 TP10.1
  CONDUCTIVE4 w0.2: v1(164.15,63.1) 164.15,63.75 163.07,64.83 160.62,64.83 159.75,65.7 v1(159.75,67.2)
  BOTTOM w0.6: v1(164.15,63.1) C56.2
SIG95: length 14.6
  TOP w0.6: v1(156.2,101.3) 155.45,100.55 R114.2
  BOTTOM w0.6: 160.4,111 160.4,109.8 155.3,104.7 155.3,101.95 155.95,101.3 v1(156.2,101.3)
SIG100: length 1.6
  TOP w0.8: D36.C R72.1
SIG101: length 1.6
  TOP w0.8: D37.A 153.75,46.85
SIG102: length 12.7
  TOP w0.7: D30.C 149.95,43.8 150.5,43.25
  TOP w0.8: 142.95,49.1 D36.A D37.C 149.35,45.4 D30.C
SIG104: length 8.3
  TOP w0.5: 144.2,47.6 143.7,47.6
  TOP w0.6: IC2.6 141.59,48.35 142.34,47.6 143.7,47.6
  TOP w0.7: 144.5,43.65 144.5,42.65 144.75,42.4 R121.2
  TOP w1: 144.5,43.7 C83.2 C82.2
SIG105: length 1.6
  TOP w0.8: 128.35,49.2 R109.1
SIG106: length 1.6
  TOP w0.8: D38.C R74.1
SIG116: length 11
  TOP w0.5: IC7.7 258.16,59.47 258.85,58.77 v1(258.85,58)
  BOTTOM w0.6: v1(258.85,58) D29.C 258.85,53.7 D58.C ; D58.C D57.A ; D58.C 257.6,52.5
SIG117: length 26
  TOP w0.5: v1(258.8,60.05) 258.8,61.45 258.25,62.01 IC7.5
  CONDUCTIVE4 w0.6: v1(258.8,60.05) 258.55,60.3 256.4,60.3 254.55,62.15 v1(254.55,69.6)
  BOTTOM w0.6: v1(254.55,69.6) 253.9,70.25 251.35,70.25 251.05,70.55 D55.A D56.C 251.05,74.95 251.5,75.4 251.5,76.6
SIG118: length 54.4
  TOP w0.6: v1(255.6,69.6) 255.6,68.5 ; v1(274.55,75) TP20.1
  CONDUCTIVE4 w0.3: v1(255.6,69.6) 255.6,70.55 260.05,75 v1(274.55,75)
  CONDUCTIVE4 w0.6: v1(255.6,69.6) v1(255.6,63.65) 264.15,63.65 265.2,62.6 v1(265.2,55.25)
  BOTTOM w0.6: v1(265.2,55.25) R25.2 R215.2 265.2,50.3 ; v1(255.6,63.65) 255.6,64.7
SIG121: length 3.4
  TOP w0.45: 257.1,60.73 C60.2 255.43,60.73
  TOP w0.6: R124.2 255.3,59.25
SIG122: length 1.5
  BOTTOM w0.4: IC8.1 C59.1
SIG124: length 3.4
  TOP w0.45: 255.43,98.83 C61.2 257.1,98.83
  TOP w0.6: R125.2 255.3,97.35
SIG126: length 5.3
  TOP w0.5: IC6.7 258.11,97.56 258.85,96.83 v1(258.85,96.45)
  BOTTOM w0.6: v1(258.85,96.45) 258.2,96.45 ; 257.3,93 D53.A D54.C
SIG127: length 27.5
  TOP w0.5: IC6.5 258.25,100.11 258.8,99.55 v1(258.8,98.1)
  CONDUCTIVE4 w0.6: v1(258.8,98.1) 255.4,98.1 253.7,99.8 253.7,106.75 v1(254.55,107.6)
  BOTTOM w0.6: 251.5,114.6 251.5,113.4 251.05,112.95 D52.C D51.A 251.05,108.55 251.35,108.25 253.9,108.25 v1(254.55,107.6)
SIG128: length 35.5
  TOP w0.6: v1(255.6,107.6) 255.6,106.5 ; v1(263.55,111.05) TP19.1
  CONDUCTIVE4 w0.3: v1(263.55,111.05) 258.65,111.05 255.6,108 v1(255.6,107.6)
  CONDUCTIVE4 w0.6: v1(255.6,107.6) 255.6,102.2 ; 255.6,102.2 v1(255.6,101.65) 256.15,101.65 ; 255.6,102.2 256.15,101.65 ; v1(264.1,98) 260.45,101.65 256.15,101.65
  BOTTOM w0.6: v1(264.1,98) R21.2 264.1,96.5 264.9,95.7 R213.2 R20.2 ; v1(255.6,101.65) 255.6,102.7
SIG136: length 1.5
  BOTTOM w0.6: IC8.5 291.25,34.6
SIG148: length 7.8
  TOP w0.3: 261.35,17.3 261.8,17.3 ; 261.35,17.3 R180.2 ; 261.35,17.3 260.25,17.3 259.8,17.75 v1(259.8,18.05)
  TOP w0.4: R180.2 R51.2
  BOTTOM w0.3: 261.5,18.68 261.12,18.68 261.02,18.77 260.5,18.77 260.08,18.35 v1(259.8,18.05)
  BOTTOM w0.4: 261.5,18.68 262.16,18.68
SIG149: length 5.4
  TOP w0.4: R181.2 R52.2 260.8,18.75 v1(260.8,18.05)
  BOTTOM w0.3: v1(260.8,18.05) 261.2,18.05 261.23,18.02 261.52,18.02
  BOTTOM w0.4: 261.52,18.02 262.2,18.02
SIG150: length 9
  TOP w0.3: v1(259.8,16.65) 259.8,14.75 260.7,13.85 261.66,13.85
  TOP w0.4: 261.8,13.9 R53.2 R182.2
  TOP w0.58: 261.66,13.85 R53.2 261.86,13.85
  BOTTOM w0.3: 261.65,17.38 261.1,17.38 261,17.27 260.43,17.27 v1(259.8,16.65)
  BOTTOM w0.4: IC10.8 261.65,17.38
SIG151: length 4.6
  BOTTOM w0.3: 261.57,16.73 261.27,16.73 260.8,16.25 260.8,13.39
  BOTTOM w0.4: 261.57,16.73 262.16,16.73
  BOTTOM w0.58: 260.8,13.19 R54.2 260.8,13.39
SIG152: length 36.8
  TOP w0.3: v1(259.85,19.35) 259.85,20.2 260.8,21.15 260.8,22.49 261.67,23.36
  TOP w0.58: 261.67,23.36 261.86,23.55
  CONDUCTIVE4 w0.2: CN10.1 275.67,18.08 267.6,26.15 260.75,26.15 259.6,25 259.6,20.85 259.85,20.6 v1(259.85,19.35)
  BOTTOM w0.3: 262.75,19.32 263.18,19.32 263.4,19.1 263.4,18.22 263.77,17.85 ; 259.8,19.35 260.21,19.32 261.48,19.32
  BOTTOM w0.4: 262.2,19.32 261.48,19.32 ; 262.55,19.32 262.75,19.32
SIG154: length 4
  BOTTOM w0.3: R44.1 263.8,21.95 263.12,21.27 262.82,21.27
  BOTTOM w0.4: 262.82,21.27 IC10.2 262.16,21.27 ; R45.2 264.6,22.05 R44.1
SIG156: length 15.2
  BOTTOM w0.3: 262.78,20.62 263.32,20.62 263.85,21.15 268.85,21.15 269.05,20.95 R43.2 ; 266.75,17.95 268.75,17.95 269.05,18.25 269.05,18.77
  BOTTOM w0.4: 262.78,20.62 IC10.3 262.16,20.62 ; R47.2 R43.2 C20.1 R42.1
  BOTTOM w0.45: C22.1 266.75,17.95
  BOTTOM w0.7: 269.05,18.77 R47.2
SIG157: length 2.7
  BOTTOM w0.4: 273.15,21.55 R42.2 R46.2
SIG168: length 4.7
  BOTTOM w0.3: 264.45,18.95 263.43,19.98 262.89,19.98
  BOTTOM w0.4: 262.89,19.98 262.3,19.98 ; R48.2 C21.2 C22.2
SIG170: length 1.4
  BOTTOM w0.4: C20.2 R46.1
SIG171: length 7.4
  TOP w0.4: R209.2 254.3,14.85 ; 254.3,14.85 254.85,14.85 ; 254.3,14.85 v1(254.6,15.15) 254.85,14.9 254.85,14.85 ; 254.85,14.85 255.7,14
  BOTTOM w0.3: v1(254.6,15.15) 254.88,15.43 255.68,15.43
  BOTTOM w0.4: R211.1 R66.2 v1(254.6,15.15) ; 255.68,15.43 IC10.14
SIG172: length 8.5
  TOP w0.3: 254.3,12.35 254.24,12.35
  TOP w0.4: R208.2 254.3,12.35 v1(254.55,12.35) 254.85,12.05 R63.1
  BOTTOM w0.3: v1(254.55,12.35) 254.55,14 255.32,14.78 255.85,14.78
  BOTTOM w0.4: v1(254.55,12.35) R64.2 R210.1 ; IC10.13 255.85,14.78
SIG173: length 9.3
  TOP w0.3: 257.04,15.85 R70.2 257.8,15.85 v1(258.1,15.55) ; 257.04,15.63 257.04,14.17 ; 257.04,13.73 257.04,12.27
  TOP w0.72: 257.04,12.27 257.04,12.05 ; 257.04,15.85 257.04,15.63 ; 257.04,14.17 257.04,13.73
  BOTTOM w0.3: 255.82,16.07 255.2,16.07 255.1,16.12 C26.2 ; v1(258.1,15.55) 257.57,16.07 257.03,16.07
  BOTTOM w0.4: IC10.15 255.82,16.07 ; R69.1 254.18,16.45 254.35,16.27 C26.2
SIG174: length 2.7
  BOTTOM w0.4: 253.5,17.95 R59.2 R67.1
SIG175: length 28.5
  CONDUCTIVE4 w0.2: v1(249.9,17.95) 252.1,15.75 252.1,13.4 254.35,11.15 257.3,11.15 259.25,13.1 v1(269.4,13.1)
  BOTTOM w0.4: v1(249.9,17.95) R59.1 ; R62.1 267.35,13.05 267.15,13.25 R60.2 ; v1(269.4,13.1) 268.3,13.1
SIG177: length 7.1
  TOP w0.4: R184.2 264.2,11.95 v1(264.1,11.85)
  BOTTOM w0.3: 264.78,13.25 262.8,13.25 262.16,13.89 262.16,14.56
  BOTTOM w0.4: v1(264.1,11.85) R61.2 R60.1
  BOTTOM w0.6: 262.16,14.68 262.16,14.56
  BOTTOM w0.7: 264.78,13.25 R60.1
SIG179: length 5.4
  TOP w0.4: R207.1 R55.2 264.3,15.85 v1(264.1,16.05)
  BOTTOM w0.3: 262.81,16.07 263.48,16.07 v1(264.1,16.05)
  BOTTOM w0.4: 262.16,16.07 IC10.10 262.81,16.07 ; v1(264.1,16.05) R57.1
SIG181: length 3.7
  TOP w0.4: v1(264.1,14.65) 264.9,13.85
  BOTTOM w0.3: 262.75,15.43 263.32,15.43 v1(264.1,14.65)
  BOTTOM w0.4: v1(264.1,14.65) R56.2
SIG183: length 4
  BOTTOM w0.4: C24.2 255.2,21.38 255.3,21.27 IC10.23
  BOTTOM w0.45: R49.2 252.8,21.65 253.07,21.38 C23.2 C24.2
SIG185: length 2.8
  BOTTOM w0.4: C67.2 176.1,37.5
  BOTTOM w0.6: IC11.3 177.05,37.5 R117.1
SIG193: length 53.7
  TOP w5: F1.1 32.1,58 19.7,45.6 CN1.1
  BOTTOM w5: CN1.1 19.7,45.6 32.1,58 F1.1
SIG199: length 34.5
  TOP w5: L11.1 70.75,33.25 C52.2 85.05,33.25 L12.2
  BOTTOM w5: L11.1 70.75,33.25 C52.2 85.05,33.25 L12.2
SIG200: length 58
  TOP w5: 77.8,20.75 77.05,20.75 68.9,12.6 68.9,10 ; 87,10.7 87,12.5 78.75,20.75 78.1,20.75
  BOTTOM w5: 78.1,20.75 78.75,20.75 87,12.5 87,10.7 ; 77.8,20.75 77.05,20.75 68.9,12.6 68.9,10
SIG205: length 36
  TOP w0.3: 160.94,88.3 161.59,87.26 163.1,85.75 175.85,85.75 176.4,85.2 176.4,84.35 ; 176.4,84.35 176.4,81.5 Q4.G 176.8,81.5 ; 176.4,84.35 176.05,84 ; 176.4,84.35 176.75,84
  TOP w0.6: 177.2,78.65 177.2,78.05 179,76.25 R33.2 179,74.25 179.1,74.15 R135.2 R134.2 ; 177.2,78.65 177.2,81.1 176.8,81.5 ; 177.2,78.65 177.8,79.25 ; 177.2,78.65 176.6,79.25
  TOP w0.8: 160.94,88.3 160.75,88.6
SIG206: length 21.1
  TOP w0.3: 159.4,81.5 158.01,83.44 154.32,87.13 153.93,88.12
  TOP w0.6: 159.4,81.5 159.4,77.5 158.4,76.5 158.4,75.6 ; 153.6,75.9 153.95,76.25 R127.2 157.05,75.3 R126.2
  TOP w0.8: 153.75,88.6 153.93,88.12
  TOP w1: R126.2 158.4,75.6
SIG223: length 2.8
  BOTTOM w0.6: R130.2 C66.2 IC11.2
SIG228: length 1.8
  BOTTOM w0.3: 234.5,21.3 233.94,21.1 233.94,21.1 233.24,20.4
  BOTTOM w0.8: IC13.5 234.5,21.3
SIG229: length 3
  BOTTOM w0.4: IC13.6 234.55,22.77 234.08,22.77 233.75,23.1 C71.2 233.28,21.8
